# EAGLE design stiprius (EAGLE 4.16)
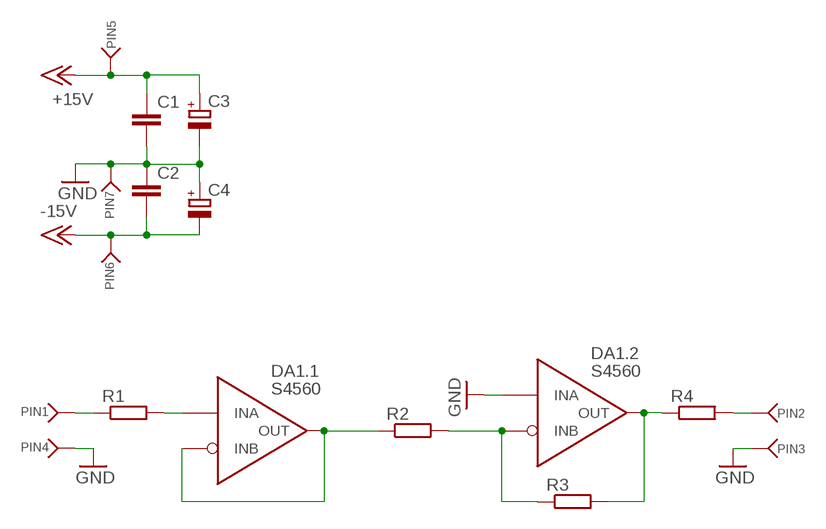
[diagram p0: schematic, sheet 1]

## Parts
C1  C-EUC1206K  [C1206K]
C2  C-EUC1206K  [C1206K]
C3  CPOL-EUC/6032-28W  [C/6032-28W]
C4  CPOL-EUC/6032-28W  [C/6032-28W]
DA1  S4560  [SO08]
PIN1  PINSMD2  [PIN-T2]
PIN2  PINSMD2  [PIN-T2]
PIN3  PINSMD2  [PIN-T2]
PIN4  PINSMD2  [PIN-T2]
PIN5  PINSMD2  [PIN-T2]
PIN6  PINSMD2  [PIN-T2]
PIN7  PINSMD2  [PIN-T2]
R1  R-EU_M1206  [M1206]
R2  R-EU_M1206  [M1206]
R3  R-EU_M1206  [M1206]
R4  R-EU_M1206  [M1206]

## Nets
GND: C1.2 C2.1 C3.- C4.+ DA1.5(.2:INA) PIN3.P$1(P) PIN4.P$1(P) PIN7.P$1(P)
N$1: DA1.3(.1:INA) R1.2
N$2: DA1.1(.1:OUT) DA1.2(.1:INB) R2.1
N$3: DA1.6(.2:INB) R2.2 R3.1
N$4: DA1.7(.2:OUT) R3.2 R4.1
N$7: PIN1.P$1(P) R1.1
N$8: PIN2.P$1(P) R4.2
VDD: C1.1 C3.+ PIN5.P$1(P) ; supply symbol labelled +15V
VEE: C2.2 C4.- PIN6.P$1(P) ; supply symbol labelled -15V

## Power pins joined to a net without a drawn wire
VDD: DA1.8(P:VDD)
VEE: DA1.4(P:VEE)

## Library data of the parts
C1 C2 = rcl:C-EU: CAPACITOR, European symbol
C3 C4 = rcl:CPOL-EU: POLARIZED CAPACITOR, European symbol
DA1 = LevoROMS:S4560
PIN1-PIN7 = LevoROMS:PIN*: PIN
R1-R4 = rcl:R-EU_: RESISTOR, European symbol

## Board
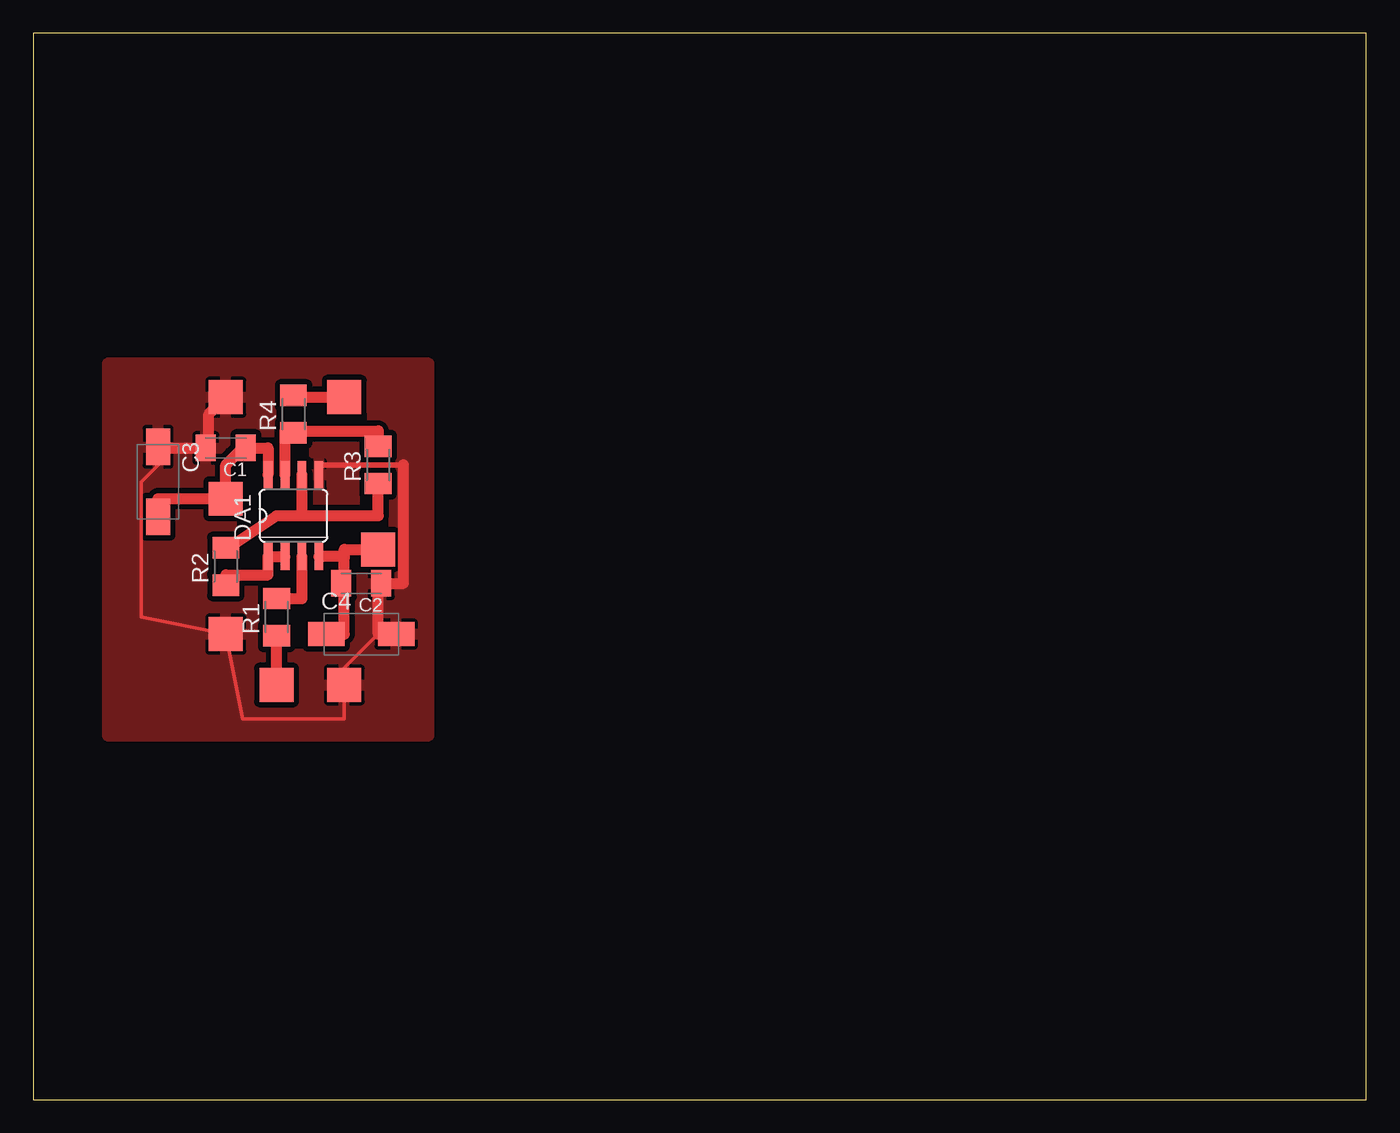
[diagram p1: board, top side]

Size 100 x 80 mm. Coordinates in mm from the lower left corner, seen from the top.
Outline: 0,0 100,0 100,80 0,80 0,0
Copper layers (1*16): Top 0.035mm / dielectric 1.5mm / Bottom 0.035mm
Design rules "default": minimum track width 10mil, minimum drill 24mil, track to track 8mil, track to pad 8mil, pad to pad 8mil, via to via 8mil, smd to smd 8mil, copper to edge 40mil, drill to drill 8mil, minimum pad ring 10mil, minimum via ring 8mil, stop-mask expansion 4mil, vias tented up to drill 0mil, thermal gap 10mil

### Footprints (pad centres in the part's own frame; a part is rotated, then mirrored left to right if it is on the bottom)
C1206K = smd 1.5 x 2: 1 -1.5,0; 2 1.5,0
C/6032-28W = smd 2.75 x 1.8: + 2.625,0; - -2.625,0
SO08 = smd 0.66 x 2.032: 1 -1.905,-3.073; 2 -0.635,-3.073; 3 0.635,-3.073; 4 1.905,-3.073; 5 1.905,3.073; 6 0.635,3.073; 7 -0.635,3.073; 8 -1.905,3.073
PIN-T2 = smd 2.54 x 2.54: P$1 0,0
M1206 = smd 1.6 x 2: 1 -1.4,0; 2 1.4,0

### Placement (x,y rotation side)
C1  14.44,48.89 180 top
C2  24.6,38.73 180 top
C3  9.36,46.35 270 top
C4  24.6,34.92 0 top
DA1  19.52,43.81 0 top
PIN1  18.25,31.11 0 top
PIN2  23.33,52.7 0 top
PIN3  23.33,31.11 0 top
PIN4  14.44,52.7 0 top
PIN5  14.44,45.08 0 top
PIN6  25.87,41.27 0 top
PIN7  14.44,34.92 0 top
R1  18.25,36.19 90 top
R2  14.44,40 90 top
R3  25.87,47.62 90 top
R4  19.52,51.43 90 top

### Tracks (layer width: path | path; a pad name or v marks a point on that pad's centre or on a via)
GND
  Top 0.254: 9.36,48.89 C3.- 9.36,47.62 8.09,46.35 8.09,36.19 PIN7.P$1 15.71,28.57 23.33,28.57 PIN3.P$1 23.33,32.38 25.87,34.92 C4.+ | C1.2 13.17,48.89
  Top 0.406: DA1.5 21.42,47.62 27.77,47.62 | 25.87,38.73 C2.1
  Top 0.813: 9.36,48.89 C1.2 | PIN4.P$1 13.17,51.43 13.17,48.89 | 25.87,34.92 25.87,38.73 27.77,38.73 27.77,47.62
  pour Top (isolate 0.406): 6.82,55.24 5.55,55.24 5.55,27.3 29.68,27.3 29.68,55.24
N$1
  Top 0.813: R1.2 20.15,37.59 DA1.3
N$2
  Top 0.406: DA1.1 17.61,40.64 | R2.1 14.44,39.37
  Top 0.813: DA1.2 DA1.1 17.61,39.37 14.44,39.37
N$3
  Top 0.254: R2.2 14.44,41.27 | R3.1 25.87,46.35
  Top 0.813: 14.44,41.27 18.25,43.81 20.15,43.81 | 20.15,43.81 25.87,43.81 R3.1 | 20.15,43.81 DA1.6
N$4
  Top 0.254: R3.2 25.87,48.89
  Top 0.406: R4.1 19.52,50.16 18.88,50.16
  Top 0.813: 19.52,50.16 25.87,50.16 R3.2 | DA1.7 18.88,50.16
N$7
  Top 0.254: R1.1 18.25,34.92
  Top 0.813: PIN1.P$1 R1.1
N$8
  Top 0.254: R4.2 19.52,52.7
  Top 0.813: 19.52,52.7 PIN2.P$1
VDD
  Top 0.254: 15.71,48.89 C1.1
  Top 0.813: 15.71,48.89 14.44,47.62 PIN5.P$1 9.36,45.08 C3.+ | C1.1 17.61,48.89 DA1.8
VEE
  Top 0.254: C4.- 23.33,34.92 | 23.33,38.73 C2.2
  Top 0.406: 23.33,40.64 23.33,40.74
  Top 0.813: 23.33,34.92 23.33,38.73 23.33,40.64 23.33,41.27 PIN6.P$1 | 23.33,40.74 DA1.4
